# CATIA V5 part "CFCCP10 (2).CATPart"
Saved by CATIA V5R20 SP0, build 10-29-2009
Part number: CFCCP10 (2)
Revision: TUTTO
Definition: NON CONOSCIUTO
Nomenclature: CFCCP10 (2)
Source: Unknown
Bounding box of the stored display mesh (mm): x -50 to 50, y -50 to 50, z 0 to 10.5
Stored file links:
  C:\Users\Utente\Desktop\IO LAVORO\3D X SITO CF\X 3D SITO CF 27-09-2020\CFCCP\CFCCP10 (2).CATPart
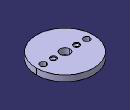
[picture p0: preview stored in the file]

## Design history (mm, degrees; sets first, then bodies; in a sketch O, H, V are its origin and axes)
Body1 "Foro Ø5.5 (5.5)-1" (main body)
  Solid1: solid without history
